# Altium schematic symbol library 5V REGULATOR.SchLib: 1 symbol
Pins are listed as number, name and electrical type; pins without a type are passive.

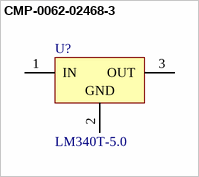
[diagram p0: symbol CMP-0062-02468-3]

## CMP-0062-02468-3
designator U?, comment LM340T-5.0
Series 3-Terminal Positive Regulators, 3-pin TO-220; Manufacturer: Texas Instruments; PowerWise: N; CompType: LDO IC; PackageTopMarking: NSUZXYTTE#*LM340T5*7805 P+
footprint NDE0003A (FM, 3-Leads, Body 10.7x4.7mm, Pitch 2.54mm)
pins: 1 IN (power), 2 GND (power), 3 OUT (power)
